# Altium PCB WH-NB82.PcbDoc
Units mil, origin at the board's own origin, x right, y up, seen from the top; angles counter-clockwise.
Board outline 6000 x 4000 mil, 2 copper layers (Top, Bottom), stack 12.7 mil thick; 1 components, 0 nets, 40 pads, 0 vias.
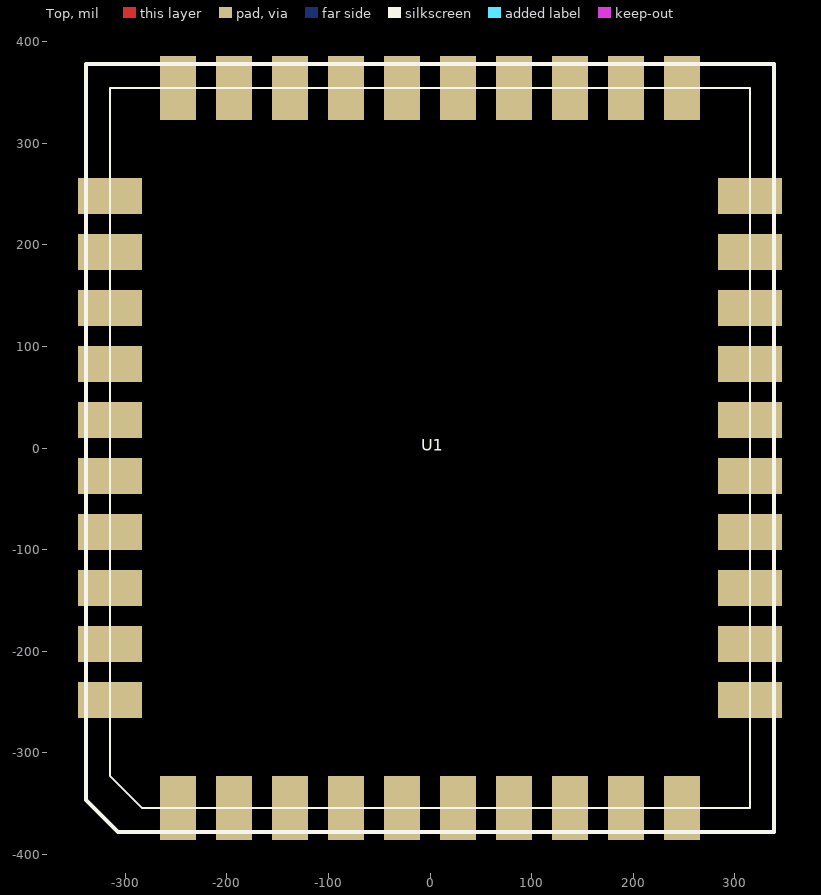
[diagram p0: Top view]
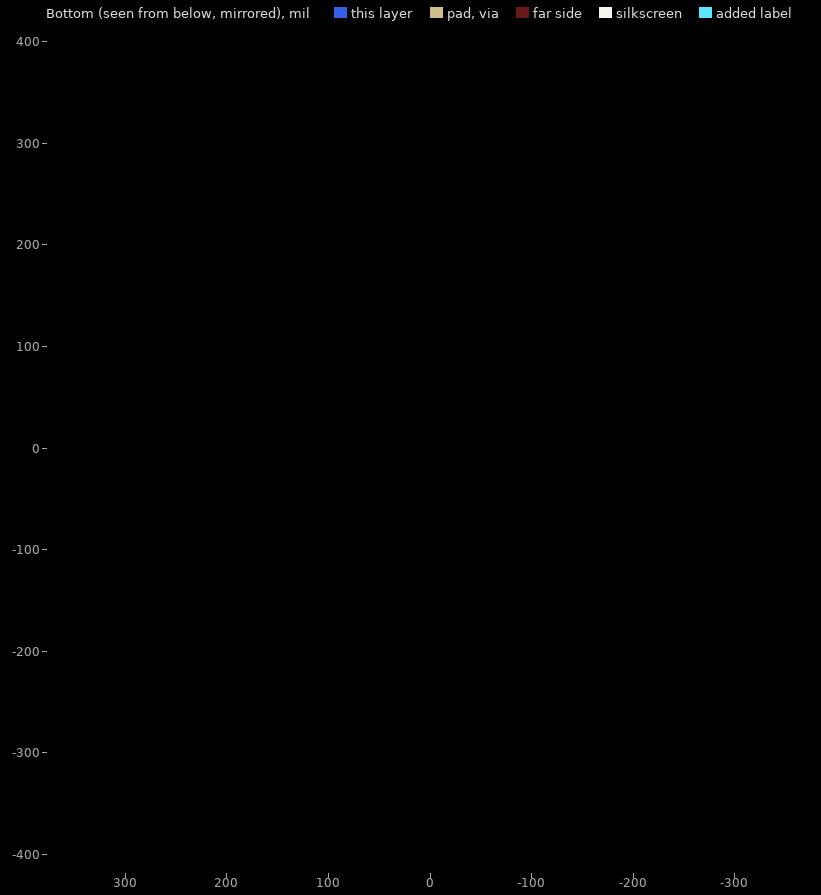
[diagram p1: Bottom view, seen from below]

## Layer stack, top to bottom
Solder Mask Top: solder mask 0.4, Solder Resist, Dk 3.5
Top: signal copper 1.35
Dielectric 1: dielectric 10, FR-4, Dk 4.3
Bottom: signal copper 1.35
Solder Mask Bottom: solder mask 0.4, Solder Resist, Dk 3.5

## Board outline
-9000,-9000 -3000,-9000 -3000,-5000 -9000,-5000

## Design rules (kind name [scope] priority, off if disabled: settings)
Clearance "Clearance - Default - DEFAULT- SMD" [IsVia vs IsSMTPin] p1: gap=6
Clearance "Clearance - Default - DEFAULT - Via" [IsVia vs IsVia] p2: gap=6
Clearance "Clearance - Default - DEFAULT - Net" [All] p3: gap=6 except(10: Text-Text)
ComponentClearance "ComponentClearance - Default - DEFAULT" [All] p1: gap=6 collisioncheckmode=3 verticalgap=10 showdistances=FALSE
FanoutControl Fanout_Small [(CompPinCount < 5)] p3: bgadir=Out bgaviamode=Centered fanoutstyle=Auto fanoutdirection=OutThenIn viagrid=1 // Fanout_Small (Default Rule)
FanoutControl Fanout_SOIC [IsSOIC] p4: bgadir=Out bgaviamode=Centered fanoutstyle=Auto fanoutdirection=Alternating viagrid=1 // Fanout_SOIC (Default Rule)
HoleToHoleClearance "HoleToHoleClearance - Default - DEFAULT" [All] p1: gap=6 allowstackedmicrovias=TRUE
Length "Default Length" [All] p1: maxlimit=50000 minlimit=0
MaxMinImpedance "Default Impedance" [All] p1: minimum=50.00 maximum=150.0
ParallelSegment "Default Parallel Segment Adjasent" [All] p1: limit=1000 gap=200
ParallelSegment "Default Parallel Segment Same Layer" [All] p2: limit=1000 gap=200
PlaneConnect "Default PlaneConnect" [All] p1: planeconnectstyle=Relief reliefexpansion=20 reliefentries=0 reliefconductorwidth=15 reliefairgap=10
PolygonConnect "PolygonConnect - Default SMT" [IsSMTPin] p1: connectstyle=Relief reliefconductorwidth=10 reliefentries=4 polygonreliefangle="45 Angle" airgapwidth=10
PolygonConnect "PolygonConnect - Default Pad" [All] p2: connectstyle=Relief reliefconductorwidth=15 reliefentries=4 polygonreliefangle="45 Angle" airgapwidth=10
RoutingLayers "RoutingLayers - Default - DEFAULT" [All] p1: top layer_v5=TRUE bottom layer_v5=TRUE
RoutingPriority "RoutingPriority - Default - DEFAULT" [All] p1: routingpriority=3
RoutingTopology "Default Routing Topology" [All] p1: topology=Shortest
RoutingVias "RoutingVias - Default - DEFAULT" [All] p1: holewidth=37 width=55 viastyle="Through Hole" minholewidth=37 minwidth=55 maxholewidth=37 maxwidth=55
SMDToCorner "SMDToCorner - Default - DEFAULT" [All] p1: distance=60000
SolderMaskExpansion [All] p1: expansion=4
Width "Default Width" [All] p1: maxlimit=6 minlimit=6 preferedwidth=6
22 further rules are at their usual default settings.

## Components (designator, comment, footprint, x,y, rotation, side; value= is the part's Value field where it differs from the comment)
U1 "WH-NB82" WH-NB82 0,0 r0 top

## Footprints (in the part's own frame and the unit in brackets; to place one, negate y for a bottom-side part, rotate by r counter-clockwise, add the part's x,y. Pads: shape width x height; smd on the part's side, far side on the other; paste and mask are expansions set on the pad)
WH-NB82 [mm]
  rect 0.9x1.6 smd mask+0.05: 1(-6.3,-9) 2(-4.9,-9) 3(-3.5,-9) 4(-2.1,-9) 5(-0.7,-9) 6(0.7,-9) 7(2.1,-9) 8(3.5,-9) 9(4.9,-9) 10(6.3,-9) 21(6.3,9) 22(4.9,9) 23(3.5,9) 24(2.1,9) 25(0.7,9) 26(-0.7,9) 27(-2.1,9) 28(-3.5,9) 29(-4.9,9) 30(-6.3,9)
  rect 1.6x0.9 smd mask+0.05: 11(8,-6.3) 12(8,-4.9) 13(8,-3.5) 14(8,-2.1) 15(8,-0.7) 16(8,0.7) 17(8,2.1) 18(8,3.5) 19(8,4.9) 20(8,6.3) 31(-8,6.3) 32(-8,4.9) 33(-8,3.5) 34(-8,2.1) 35(-8,0.7) 36(-8,-0.7) 37(-8,-2.1) 38(-8,-3.5) 39(-8,-4.9) 40(-8,-6.3)
  silkscreen extent -8.6,-9.6 8.6,9.6

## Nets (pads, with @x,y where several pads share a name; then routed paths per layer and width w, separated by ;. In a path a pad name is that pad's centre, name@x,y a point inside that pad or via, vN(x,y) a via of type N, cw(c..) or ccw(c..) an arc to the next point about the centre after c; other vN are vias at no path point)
pads on no net: U1.1 U1.2 U1.3 U1.4 U1.5 U1.6 U1.7 U1.8 U1.9 U1.10 U1.11 U1.12 U1.13 U1.14 U1.15 U1.16 U1.17 U1.18 U1.19 U1.20 U1.21 U1.22 U1.23 U1.24 U1.25 U1.26 U1.27 U1.28 U1.29 U1.30 U1.31 U1.32 U1.33 U1.34 U1.35 U1.36 U1.37 U1.38 U1.39 U1.40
